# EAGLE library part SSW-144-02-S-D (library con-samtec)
THROUGH-HOLE .025" SQ POST SOCKET Source: Samtec SSW.pdf
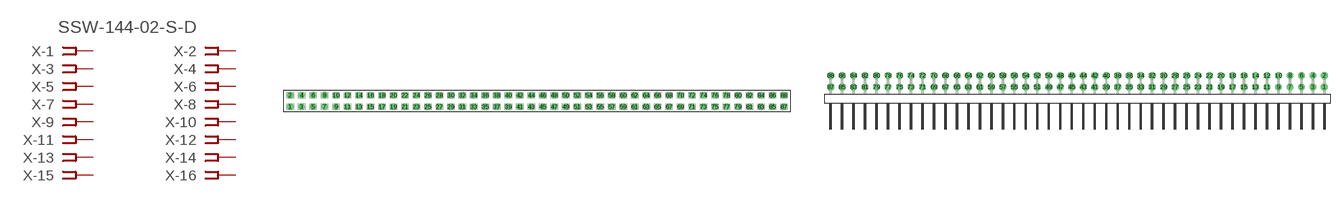
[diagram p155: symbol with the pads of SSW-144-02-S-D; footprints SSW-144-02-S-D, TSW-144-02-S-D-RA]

Designator prefix X; gates -1=FPINV -2=FPIN -3=FPIN -4=FPIN -5=FPIN -6=FPIN -7=FPIN -8=FPIN -9=FPIN -10=FPIN -11=FPIN -12=FPIN -13=FPIN -14=FPIN -15=FPIN -16=FPIN -17=FPIN -18=FPIN -19=FPIN -20=FPIN -21=FPIN -22=FPIN -23=FPIN -24=FPIN -25=FPIN -26=FPIN -27=FPIN -28=FPIN -29=FPIN -30=FPIN -31=FPIN -32=FPIN -33=FPIN -34=FPIN -35=FPIN -36=FPIN -37=FPIN -38=FPIN -39=FPIN -40=FPIN -41=FPIN -42=FPIN -43=FPIN -44=FPIN -45=FPIN -46=FPIN -47=FPIN -48=FPIN -49=FPIN -50=FPIN -51=FPIN -52=FPIN -53=FPIN -54=FPIN -55=FPIN -56=FPIN -57=FPIN -58=FPIN -59=FPIN -60=FPIN -61=FPIN -62=FPIN -63=FPIN -64=FPIN -65=FPIN -66=FPIN -67=FPIN -68=FPIN -69=FPIN -70=FPIN -71=FPIN -72=FPIN -73=FPIN -74=FPIN -75=FPIN -76=FPIN -77=FPIN -78=FPIN -79=FPIN -80=FPIN -81=FPIN -82=FPIN -83=FPIN -84=FPIN -85=FPIN -86=FPIN -87=FPIN -88=FPIN

## SSW-144-02-S-D (MPN: SSW-144-02-S-D; OC_FARNELL: unknown; OC_NEWARK: 11P9999)  [SSW-144-02-S-D]
1  -1:1  pas
2  -2:1  pas
3  -3:1  pas
4  -4:1  pas
5  -5:1  pas
6  -6:1  pas
7  -7:1  pas
8  -8:1  pas
9  -9:1  pas
10  -10:1  pas
11  -11:1  pas
12  -12:1  pas
13  -13:1  pas
14  -14:1  pas
15  -15:1  pas
16  -16:1  pas
17  -17:1  pas
18  -18:1  pas
19  -19:1  pas
20  -20:1  pas
21  -21:1  pas
22  -22:1  pas
23  -23:1  pas
24  -24:1  pas
25  -25:1  pas
26  -26:1  pas
27  -27:1  pas
28  -28:1  pas
29  -29:1  pas
30  -30:1  pas
31  -31:1  pas
32  -32:1  pas
33  -33:1  pas
34  -34:1  pas
35  -35:1  pas
36  -36:1  pas
37  -37:1  pas
38  -38:1  pas
39  -39:1  pas
40  -40:1  pas
41  -41:1  pas
42  -42:1  pas
43  -43:1  pas
44  -44:1  pas
45  -45:1  pas
46  -46:1  pas
47  -47:1  pas
48  -48:1  pas
49  -49:1  pas
50  -50:1  pas
51  -51:1  pas
52  -52:1  pas
53  -53:1  pas
54  -54:1  pas
55  -55:1  pas
56  -56:1  pas
57  -57:1  pas
58  -58:1  pas
59  -59:1  pas
60  -60:1  pas
61  -61:1  pas
62  -62:1  pas
63  -63:1  pas
64  -64:1  pas
65  -65:1  pas
66  -66:1  pas
67  -67:1  pas
68  -68:1  pas
69  -69:1  pas
70  -70:1  pas
71  -71:1  pas
72  -72:1  pas
73  -73:1  pas
74  -74:1  pas
75  -75:1  pas
76  -76:1  pas
77  -77:1  pas
78  -78:1  pas
79  -79:1  pas
80  -80:1  pas
81  -81:1  pas
82  -82:1  pas
83  -83:1  pas
84  -84:1  pas
85  -85:1  pas
86  -86:1  pas
87  -87:1  pas
88  -88:1  pas

## SSW-144-02-S-D-RA (OC_FARNELL: unknown; OC_NEWARK: unknown)  [TSW-144-02-S-D-RA]
Pads as for SSW-144-02-S-D

## Footprint SSW-144-02-S-D (pad centres in mm)
THROUGH-HOLE .025" SQ POST SOCKET Source: Samtec SSW.pdf
drill 1 pad 1.5 octagon: 1 -54.61,-1.27; 2 -54.61,1.27; 3 -52.07,-1.27; 4 -52.07,1.27; 5 -49.53,-1.27; 6 -49.53,1.27; 7 -46.99,-1.27; 8 -46.99,1.27; 9 -44.45,-1.27; 10 -44.45,1.27; 11 -41.91,-1.27; 12 -41.91,1.27; 13 -39.37,-1.27; 14 -39.37,1.27; 15 -36.83,-1.27; 16 -36.83,1.27; 17 -34.29,-1.27; 18 -34.29,1.27; 19 -31.75,-1.27; 20 -31.75,1.27; 21 -29.21,-1.27; 22 -29.21,1.27; 23 -26.67,-1.27; 24 -26.67,1.27; 25 -24.13,-1.27; 26 -24.13,1.27; 27 -21.59,-1.27; 28 -21.59,1.27; 29 -19.05,-1.27; 30 -19.05,1.27; 31 -16.51,-1.27; 32 -16.51,1.27; 33 -13.97,-1.27; 34 -13.97,1.27; 35 -11.43,-1.27; 36 -11.43,1.27; 37 -8.89,-1.27; 38 -8.89,1.27; 39 -6.35,-1.27; 40 -6.35,1.27; 41 -3.81,-1.27; 42 -3.81,1.27; 43 -1.27,-1.27; 44 -1.27,1.27; 45 1.27,-1.27; 46 1.27,1.27; 47 3.81,-1.27; 48 3.81,1.27; 49 6.35,-1.27; 50 6.35,1.27; 51 8.89,-1.27; 52 8.89,1.27; 53 11.43,-1.27; 54 11.43,1.27; 55 13.97,-1.27; 56 13.97,1.27; 57 16.51,-1.27; 58 16.51,1.27; 59 19.05,-1.27; 60 19.05,1.27; 61 21.59,-1.27; 62 21.59,1.27; 63 24.13,-1.27; 64 24.13,1.27; 65 26.67,-1.27; 66 26.67,1.27; 67 29.21,-1.27; 68 29.21,1.27; 69 31.75,-1.27; 70 31.75,1.27; 71 34.29,-1.27; 72 34.29,1.27; 73 36.83,-1.27; 74 36.83,1.27; 75 39.37,-1.27; 76 39.37,1.27; 77 41.91,-1.27; 78 41.91,1.27; 79 44.45,-1.27; 80 44.45,1.27; 81 46.99,-1.27; 82 46.99,1.27; 83 49.53,-1.27; 84 49.53,1.27; 85 52.07,-1.27; 86 52.07,1.27; 87 54.61,-1.27; 88 54.61,1.27

## Footprint TSW-144-02-S-D-RA (pad centres in mm)
THROUGH-HOLE .025" SQ POST HEADER Source: Samtec TSW.pdf
drill 1 pad 1.5 octagon: 1 54.61,1.524; 2 54.61,4.064; 3 52.07,1.524; 4 52.07,4.064; 5 49.53,1.524; 6 49.53,4.064; 7 46.99,1.524; 8 46.99,4.064; 9 44.45,1.524; 10 44.45,4.064; 11 41.91,1.524; 12 41.91,4.064; 13 39.37,1.524; 14 39.37,4.064; 15 36.83,1.524; 16 36.83,4.064; 17 34.29,1.524; 18 34.29,4.064; 19 31.75,1.524; 20 31.75,4.064; 21 29.21,1.524; 22 29.21,4.064; 23 26.67,1.524; 24 26.67,4.064; 25 24.13,1.524; 26 24.13,4.064; 27 21.59,1.524; 28 21.59,4.064; 29 19.05,1.524; 30 19.05,4.064; 31 16.51,1.524; 32 16.51,4.064; 33 13.97,1.524; 34 13.97,4.064; 35 11.43,1.524; 36 11.43,4.064; 37 8.89,1.524; 38 8.89,4.064; 39 6.35,1.524; 40 6.35,4.064; 41 3.81,1.524; 42 3.81,4.064; 43 1.27,1.524; 44 1.27,4.064; 45 -1.27,1.524; 46 -1.27,4.064; 47 -3.81,1.524; 48 -3.81,4.064; 49 -6.35,1.524; 50 -6.35,4.064; 51 -8.89,1.524; 52 -8.89,4.064; 53 -11.43,1.524; 54 -11.43,4.064; 55 -13.97,1.524; 56 -13.97,4.064; 57 -16.51,1.524; 58 -16.51,4.064; 59 -19.05,1.524; 60 -19.05,4.064; 61 -21.59,1.524; 62 -21.59,4.064; 63 -24.13,1.524; 64 -24.13,4.064; 65 -26.67,1.524; 66 -26.67,4.064; 67 -29.21,1.524; 68 -29.21,4.064; 69 -31.75,1.524; 70 -31.75,4.064; 71 -34.29,1.524; 72 -34.29,4.064; 73 -36.83,1.524; 74 -36.83,4.064; 75 -39.37,1.524; 76 -39.37,4.064; 77 -41.91,1.524; 78 -41.91,4.064; 79 -44.45,1.524; 80 -44.45,4.064; 81 -46.99,1.524; 82 -46.99,4.064; 83 -49.53,1.524; 84 -49.53,4.064; 85 -52.07,1.524; 86 -52.07,4.064; 87 -54.61,1.524; 88 -54.61,4.064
